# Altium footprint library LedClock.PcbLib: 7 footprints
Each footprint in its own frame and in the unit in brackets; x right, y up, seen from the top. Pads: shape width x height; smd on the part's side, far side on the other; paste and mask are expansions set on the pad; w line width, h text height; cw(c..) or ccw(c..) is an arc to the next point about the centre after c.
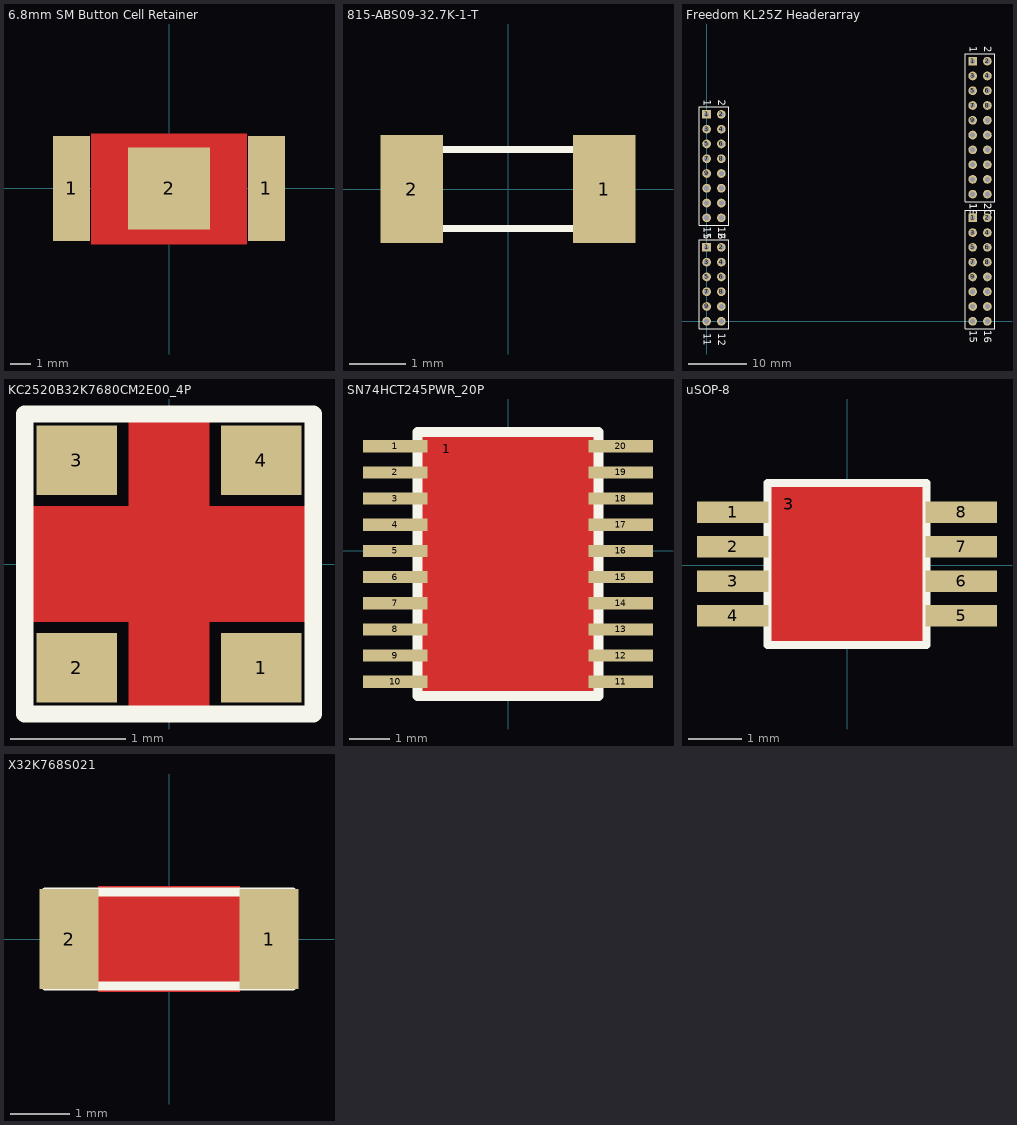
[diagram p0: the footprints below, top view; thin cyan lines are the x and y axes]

## 6.8mm SM Button Cell Retainer [mm]
pads (3):
  rect 1.78x5.08 smd: 1(-4.7,0) 1(4.7,0)
  rect 3.96x3.96 smd: 2(0,0)
Top Layer:
  pour cut-out: -3.75,2.65 3.75,2.65 3.75,-2.7 -3.75,-2.7

## 815-ABS09-32.7K-1-T [mm] "Quarze 32.768KHz 12.5pF -40C +85C 10ppm"
pads (2):
  rect 1.1x1.9 smd: 1(1.7,0) 2(-1.7,0)
Top Overlay:
  lines w0.127: -2.05,-0.7 -2.05,0.7 2.05,0.7 2.05,-0.7 -2.05,-0.7

## Freedom KL25Z Headerarray [mm] "Headerarray KL25Z Shield"
pads (64):
  rect 1.5x1.5 hole 0.9: 1(0,12.7) 1(0,35.56) 1(45.72,17.78) 1(45.72,44.704)
  round 1.5 hole 0.9: 2(2.54,12.7) 2(2.54,35.56) 2(48.26,17.78) 2(48.26,44.704) 3(0,10.16) 3(0,33.02) 3(45.72,15.24) 3(45.72,42.164) 4(2.54,10.16) 4(2.54,33.02) 4(48.26,15.24) 4(48.26,42.164) 5(0,7.62) 5(0,30.48) 5(45.72,12.7) 5(45.72,39.624) 6(2.54,7.62) 6(2.54,30.48) 6(48.26,12.7) 6(48.26,39.624) 7(0,5.08) 7(0,27.94) 7(45.72,10.16) 7(45.72,37.084) 8(2.54,5.08) 8(2.54,27.94) 8(48.26,10.16) 8(48.26,37.084) 9(0,2.54) 9(0,25.4) 9(45.72,7.62) 9(45.72,34.544) 10(2.54,2.54) 10(2.54,25.4) 10(48.26,7.62) 10(48.26,34.544) 11(0,0) 11(0,22.86) 11(45.72,5.08) 11(45.72,32.004) 12(2.54,0) 12(2.54,22.86) 12(48.26,5.08) 12(48.26,32.004) 13(0,20.32) 13(45.72,2.54) 13(45.72,29.464) 14(2.54,20.32) 14(48.26,2.54) 14(48.26,29.464) 15(0,17.78) 15(45.72,0) 15(45.72,26.924) 16(2.54,17.78) 16(48.26,0) 16(48.26,26.924) 17(45.72,24.384) 18(48.26,24.384) 19(45.72,21.844) 20(48.26,21.844)
Top Overlay:
  lines w0.2: -1.27,-1.27 -1.27,13.97 3.81,13.97 3.81,-1.27 -1.27,-1.27 ; -1.27,16.51 3.81,16.51 3.81,36.83 -1.27,36.83 -1.27,16.51 ; 44.45,-1.27 49.53,-1.27 49.53,19.05 44.45,19.05 44.45,-1.27 ; 44.45,20.574 49.53,20.574 49.53,44.069 49.53,45.974 44.45,45.974 44.45,44.069 44.45,20.574
  text "20" at 47.752,20.32 h1.27
  text "19" at 45.212,20.32 h1.27
  text "1" at 45.212,47.244 h1.27
  text "2" at 47.752,47.244 h1.27
  text "2" at 47.752,20.32 h1.27
  text "1" at 45.212,20.32 h1.27
  text "15" at 45.212,-1.524 h1.27
  text "16" at 47.752,-1.524 h1.27
  text "2" at 2.032,38.1 h1.27
  text "1" at -0.508,38.1 h1.27
  text "15" at -0.508,16.256 h1.27
  text "16" at 2.032,16.256 h1.27
  text "12" at 2.032,-2.032 h1.27
  text "1" at -0.508,-3.048 h1.27
  text "1" at -0.508,-2.032 h1.27
  text "1" at -0.508,15.24 h1.27
  text "2" at 2.032,15.24 h1.27

## KC2520B32K7680CM2E00_4P [mm]
pads (4):
  rect 0.7x0.6 smd: 1(0.8,-0.9) 2(-0.8,-0.9) 3(-0.8,0.9) 4(0.8,0.9)
Top Layer:
  pour cut-out: -0.35,1.25 -0.35,0.5 -1.2,0.5 -1.2,-0.5 -0.35,-0.5 -0.35,-1.25 0.35,-1.25 0.35,-0.5 1.2,-0.5 1.2,0.5 0.35,0.5 0.35,1.25
Top Overlay:
  lines w0.15: -1.25,-1.3 1.25,-1.3 1.25,1.3 -1.25,1.3 -1.25,-1.3

## SN74HCT245PWR_20P [mm]
pads (21):
  rect 1.6x0.3 smd mask+0.07: 1(-2.8,2.6) 2(-2.8,1.95) 3(-2.8,1.3) 4(-2.8,0.65) 5(-2.8,0) 6(-2.8,-0.65) 7(-2.8,-1.3) 8(-2.8,-1.95) 9(-2.8,-2.6) 10(-2.8,-3.25) 11(2.8,-3.25) 12(2.8,-2.6) 13(2.8,-1.95) 14(2.8,-1.3) 15(2.8,-0.65) 16(2.8,0) 17(2.8,0.65) 18(2.8,1.3) 19(2.8,1.95) 20(2.8,2.6)
  round 0.4 on Top Overlay: 1(-1.524,2.54)
Top Layer:
  pour cut-out: -2.15,2.85 2.15,2.85 2.15,-3.5 -2.15,-3.5
Top Overlay:
  lines w0.254: -2.25,-3.6 2.25,-3.6 2.25,2.95 -2.25,2.95 -2.25,-3.6

## uSOP-8 [mm] "3x3mm, 0.65mm"
pads (9):
  rect 1.35x0.4 smd: 1(-2.15,1) 2(-2.15,0.35) 3(-2.15,-0.3) 4(-2.15,-0.95) 5(2.15,-0.95) 6(2.15,-0.3) 7(2.15,0.35) 8(2.15,1)
  round 0.4 on Top Overlay: 3(-1.1,1.15)
Top Layer:
  pour cut-out: -1.45,1.5 1.45,1.5 1.45,-1.45 -1.45,-1.45
Top Overlay:
  lines w0.15: -1.5,-1.5 1.5,-1.5 1.5,1.55 -1.5,1.55 -1.5,-1.5

## X32K768S021 [mm]
pads (2):
  rect 1x1.7 smd: 1(1.7,0) 2(-1.7,0)
Top Layer:
  pour cut-out: -1.2,0.9 1.2,0.9 1.2,-0.9 -1.2,-0.9
Top Overlay:
  lines w0.15: -2.1,-0.8 -2.1,0.8 2.1,0.8 2.1,-0.8 -2.1,-0.8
